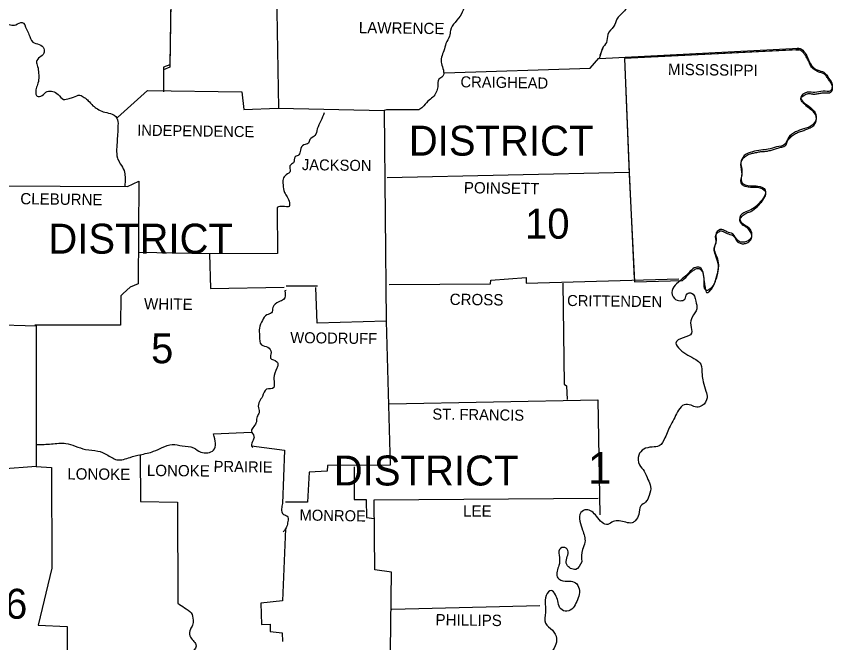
# Model space of a CAD drawing. Extents: x 191 to 3403, y 68 to 2102.
# Drawn here: x 2999.8 to 3303.9, y 1667 to 1900.2 of the extents above; entities that cross this region are included whole.
import ezdxf

# ---------------------------------------------------------------- set-up
doc = ezdxf.new("R2010")
doc.units = 0
for name, color, linetype in [('1', 7, 'Continuous'), ('2', 7, 'Continuous'), ('3', 7, 'Continuous'), ('S_MISC_BOUNDARY', 7, 'Continuous')]:
    doc.layers.add(name, color=color, linetype=linetype)

msp = doc.modelspace()

# ---------------------------------------------------------------- linework, layer by layer
at = {"layer": '1'}
for p, q in [((3216.98, 1884.51), (3218.15, 1888.13)), ((3217.27, 1885.68), (3218.45, 1888.52)), ((3100.35, 1799.78), (3112, 1799.78))]:
    msp.add_line(p, q, dxfattribs=at)
for points in [[(3000.75, 1956.03), (3000.95, 1932.74), (2999.28, 1932.64), (2999.58, 1908.28), (2992.73, 1907.3), (2993.32, 1900.75), (2995.66, 1897.71), (2995.47, 1889.98), (2982.16, 1889.5), (2981.67, 1877.56), (2969.54, 1877.17), (2968.95, 1862.69), (2969.64, 1861.51), (2969.93, 1838.42), (2990.87, 1837.05), (2990.58, 1785.49), (3007.21, 1785), (3007.21, 1732.56), (2994.1, 1731.58), (2993.12, 1720.04), (2971.11, 1719.94)], [(3090.67, 1957.4), (3090.37, 1955.05), (3092.33, 1954.76), (3092.23, 1953.58), (3094.48, 1953.09), (3094.68, 1951.53), (3095.75, 1950.84), (3096.05, 1946.15), (3101.63, 1945.56), (3101.63, 1941.35), (3103.68, 1941.06), (3103.68, 1939.39), (3105.44, 1938.9), (3105.34, 1933.23), (3106.91, 1932.94), (3107.3, 1920.12), (3098.98, 1919.34), (3099.08, 1916.6), (3096.54, 1916.5), (3097.42, 1866.01), (3136.85, 1865.13), (3137.53, 1786.66), (3111.8, 1785.98), (3111.31, 1799.19)], [(3055.64, 1918.95), (3055.44, 1913.27), (3058.18, 1913.07), (3058.28, 1906.81), (3057.3, 1906.81), (3056.91, 1882.16), (3054.66, 1881.18), (3054.66, 1872.96)], [(3055.64, 1918.06), (3055.44, 1912.39), (3058.18, 1912.19), (3058.28, 1905.93), (3057.3, 1905.93), (3056.91, 1881.28), (3054.66, 1880.3), (3054.66, 1872.08)], [(3216.98, 1884.51), (3291.24, 1888.32)], [(3159.25, 1879.12), (3213.55, 1880.89), (3216.78, 1884.6)], [(3226.37, 1884.41), (3228.04, 1842.04), (3229.99, 1802.61)], [(3037.44, 1862.49), (3048.6, 1872.57), (3083.82, 1872.08), (3084.5, 1865.52), (3097.32, 1866.01)], [(3149.67, 1865.33), (3137.73, 1865.33), (3136.85, 1865.13)], [(3228.04, 1842.04), (3137.92, 1839.99)], [(2990.87, 1837.05), (3041.16, 1836.76), (3045.46, 1838.81), (3045.17, 1800.56), (3042.24, 1799.29), (3039.59, 1797.04), (3038.71, 1796.16), (3038.62, 1785.2), (3006.62, 1785.2)], [(3096.93, 1829.03), (3097.12, 1811.81), (3071.69, 1811.71), (3045.56, 1812.2)], [(3071.69, 1811.71), (3072.08, 1798.89), (3099.57, 1799.38)], [(3138.71, 1800.36), (3176.47, 1800.56), (3176.57, 1801.93), (3189.68, 1802.91), (3189.68, 1800.85), (3246.63, 1802.42)], [(3203.38, 1800.85), (3203.87, 1763.18), (3204.75, 1762.6), (3205.04, 1757.51)], [(3100.35, 1798.11), (3099.86, 1798.01)], [(3137.53, 1786.66), (3139, 1733.05), (3115.71, 1732.95), (3115.62, 1730.8), (3108.87, 1730.41), (3108.28, 1719.25), (3100.06, 1719.25)], [(3138.71, 1755.85), (3216.39, 1757.41)], [(3216.39, 1757.41), (3217.18, 1714.56)], [(3073.25, 1744.69), (3087.44, 1745.38)], [(3087.44, 1740.29), (3099.67, 1738.72), (3098.98, 1718.76)], [(3045.86, 1737.06), (3046.05, 1719.55), (3059.85, 1719.25), (3059.95, 1681.68)], [(3007.21, 1732.56), (3012.88, 1732.17), (3012.98, 1694.79), (3007.89, 1673.56), (3018.75, 1673.07), (3018.66, 1655.07)], [(3125.69, 1732.46), (3125.6, 1720.33), (3130.1, 1720.33), (3130.29, 1713.58), (3133.13, 1713.28)], [(3138.71, 1633.54), (3146.34, 1634.03), (3146.24, 1653.9), (3139.1, 1654.38), (3139.49, 1693.23), (3133.33, 1694.11), (3133.13, 1720.23), (3216.59, 1720.82)], [(3100.06, 1709.37), (3098.89, 1682.56), (3090.86, 1681.68), (3091.06, 1673.76), (3094.29, 1673.85), (3094.39, 1671.11), (3098.79, 1670.63), (3098.89, 1667.4)], [(3139.69, 1679.43), (3194.87, 1680.8)]]:
    msp.add_lwpolyline(points, dxfattribs=at)
for points in [[(3240.46, 1960.92), (3240.95, 1956.61), (3242.32, 1954.36), (3242.52, 1950.25), (3244.18, 1948.49), (3247.02, 1946.73), (3249.56, 1943.89), (3250.15, 1940.57), (3249.36, 1937.14), (3249.17, 1933.33), (3248.78, 1930), (3248.19, 1926.97), (3245.84, 1924.52), (3243.59, 1922.76), (3241.54, 1920.71), (3240.07, 1918.55), (3237.53, 1916.21), (3234.98, 1913.76), (3232.93, 1911.61), (3230.87, 1908.87), (3229.89, 1905.83), (3227.64, 1903.68), (3225.88, 1901.73), (3223.53, 1899.08), (3222.36, 1896.44), (3220.11, 1893.41), (3219.62, 1890.47), (3218.15, 1888.13), (3218.06, 1887.73)], [(3168.25, 1906.13), (3166.79, 1903.78), (3165.61, 1901.04), (3163.26, 1897.91), (3161.5, 1894.88), (3161.21, 1892.82), (3159.84, 1890.08), (3159.06, 1887.34), (3158.18, 1884.99), (3158.18, 1882.55), (3158.86, 1880.1), (3158.67, 1877.85), (3157.2, 1876.78), (3156.81, 1873.94), (3156.22, 1871.98), (3154.95, 1870.03), (3153.09, 1868.56), (3151.13, 1866.31), (3149.67, 1865.33)], [(2995.66, 1897.71), (2999.58, 1897.03), (3001.93, 1897.91), (3003.59, 1895.37), (3004.47, 1893.41), (3005.94, 1890.57), (3008.29, 1889.69), (3010.05, 1888.13), (3010.05, 1886.46), (3008.48, 1884.9), (3007.31, 1883.33), (3007.7, 1881.47), (3008.09, 1878.93), (3008.09, 1876.48), (3007.5, 1874.23), (3007.01, 1872.18), (3007.5, 1870.42), (3009.36, 1870.71), (3011.32, 1872.18), (3013.37, 1872.18), (3015.33, 1871.1), (3017.38, 1869.24), (3019.44, 1869.63), (3021.1, 1870.12), (3023.45, 1870.81), (3025.11, 1869.93), (3026.58, 1868.75), (3028.34, 1866.89), (3030.01, 1865.72), (3032.16, 1864.64), (3034.8, 1863.96), (3037.25, 1862.3), (3037.64, 1859.46), (3037.54, 1857.01), (3037.34, 1853.98), (3037.15, 1850.65), (3037.44, 1847.42), (3038.52, 1845.27), (3039.89, 1842.73), (3040.28, 1840.38), (3040.18, 1836.66)], [(3290.16, 1888.22), (3291.24, 1888.32), (3294.57, 1884.8), (3296.03, 1881.86), (3298.19, 1880.2), (3300.63, 1879.32), (3302.49, 1877.07), (3303.76, 1874.62), (3303.08, 1872.47), (3300.34, 1872.28), (3297.31, 1871.79), (3294.37, 1871.88), (3292.02, 1869.93), (3294.18, 1867.29), (3297.01, 1864.84), (3297.8, 1862.2), (3296.23, 1859.65), (3293.1, 1858.28), (3290.07, 1857.11), (3287.33, 1854.76), (3286.05, 1852.51), (3283.02, 1851.53), (3279.89, 1850.65), (3277.15, 1850.36), (3274.02, 1849.77), (3270.99, 1848.3), (3269.72, 1845.76), (3270.11, 1842.14), (3270.01, 1838.32), (3273.24, 1837.05), (3276.08, 1836.95), (3278.81, 1835.49), (3278.52, 1833.33), (3276.47, 1830.6), (3274.02, 1828.44), (3271.57, 1827.37), (3269.32, 1825.31), (3270.11, 1823.26), (3272.16, 1821.89), (3273.63, 1819.64), (3273.43, 1817.58), (3271.09, 1816.11), (3268.54, 1816.7), (3266.68, 1819.15), (3264.53, 1819.93), (3262.67, 1820.81), (3260.52, 1819.54), (3260.52, 1816.7), (3259.74, 1813.67), (3260.42, 1811.42), (3261.3, 1808.29), (3261.2, 1805.94), (3260.42, 1802.61), (3258.76, 1799.19), (3256.8, 1798.11), (3256.02, 1801.83), (3255.63, 1804.86), (3254.45, 1806.62), (3252.89, 1806.72), (3250.83, 1805.25), (3248.58, 1803), (3245.74, 1800.56), (3244.08, 1798.11), (3244.96, 1795.08), (3247.11, 1794.3), (3248.78, 1794.88), (3249.66, 1796.84), (3251.32, 1797.13), (3252.89, 1794.1)], [(3114.44, 1864.25), (3113.27, 1861.22), (3111.9, 1858.28), (3111.02, 1855.74), (3109.16, 1854.27), (3108.57, 1852.9), (3106.91, 1852.32), (3105.64, 1850.36), (3105.05, 1848.6), (3103.68, 1847.82), (3103, 1845.66), (3101.72, 1844.49), (3101.82, 1842.53), (3100.35, 1841.16), (3099.18, 1839.6), (3099.18, 1837.44), (3099.67, 1834.61), (3100.65, 1832.94), (3101.53, 1830.79), (3101.43, 1829.42), (3098.98, 1829.42), (3096.93, 1829.03)], [(3099.86, 1798.01), (3099.37, 1794.79), (3097.52, 1793.91), (3095.36, 1791.75), (3094.87, 1789.8), (3093.11, 1789.01), (3091.45, 1786.96), (3090.37, 1784.12), (3090.37, 1781.19), (3091.06, 1777.86), (3093.5, 1776.98), (3094.68, 1775.02), (3094.48, 1772.97), (3096.83, 1771.6), (3097.22, 1770.42), (3096.83, 1769.15), (3095.75, 1765.53), (3095.85, 1763.09), (3095.66, 1762.01), (3093.02, 1761.32), (3091.45, 1758.68), (3090.37, 1756.82), (3089.98, 1754.38), (3090.28, 1752.62), (3089.49, 1751.25), (3089.2, 1749.19), (3088.22, 1747.43), (3087.34, 1745.77), (3088.32, 1743.81), (3088.03, 1742.44), (3087.44, 1740.29), (3087.93, 1739.6)], [(3252.89, 1794.1), (3253.28, 1791.26), (3251.62, 1788.23), (3251.03, 1785.2), (3251.32, 1782.16), (3248.19, 1780.5), (3245.45, 1778.54), (3247.02, 1776.2), (3249.95, 1774.04), (3252.89, 1772.38), (3254.75, 1770.72), (3255.24, 1766.71), (3255.72, 1764.16), (3256.7, 1760.64), (3257.09, 1758.19), (3255.33, 1755.26), (3253.28, 1754.67), (3251.13, 1755.36), (3248.58, 1755.55), (3246.53, 1753.59), (3245.06, 1750.86), (3243.59, 1748.12), (3242.52, 1745.77), (3241.44, 1743.22), (3239.29, 1740.29), (3236.65, 1739.8), (3233.51, 1739.02), (3231.66, 1736.86), (3231.95, 1733.24), (3233.71, 1730.8), (3235.08, 1727.76), (3236.06, 1725.12), (3235.57, 1721.8), (3234.2, 1719.35), (3232.44, 1717.88), (3231.66, 1714.75), (3230.38, 1712.4), (3229.21, 1711.62), (3226.86, 1711.82), (3224.32, 1712.31), (3222.16, 1712.11), (3220.11, 1711.03), (3218.06, 1711.72), (3215.9, 1714.07), (3214.14, 1715.83), (3212.19, 1716.51), (3210.13, 1715.44), (3209.74, 1712.21), (3210.72, 1708.88), (3211.6, 1704.38), (3210.72, 1701.64), (3210.42, 1697.14)], [(3007.4, 1740.78), (3012.88, 1740.97), (3018.26, 1741.17), (3021.69, 1740.19), (3025.6, 1738.92), (3030.2, 1738.33), (3033.43, 1737.06), (3037.25, 1735.1), (3042.14, 1735.98), (3045.95, 1736.96), (3050.94, 1738.23), (3054.17, 1739.6), (3057.89, 1740.78), (3061.61, 1740.29), (3065.82, 1739.51), (3068.46, 1737.94), (3073.25, 1738.63), (3073.25, 1744.69)], [(3098.98, 1718.76), (3098.59, 1716.81), (3099.37, 1714.75), (3100.74, 1714.07), (3100.94, 1712.11), (3100.45, 1710.15), (3100.06, 1709.37), (3099.18, 1708.2)], [(3210.42, 1697.14), (3208.17, 1694.3), (3204.85, 1696.06), (3204.85, 1698.41), (3205.34, 1700.86), (3204.16, 1702.42), (3202.11, 1701.74), (3202.11, 1698.71), (3201.91, 1695.77), (3201.32, 1691.56), (3202.69, 1690.29), (3205.83, 1689.9), (3208.08, 1689.31), (3209.45, 1687.06), (3209.35, 1684.32), (3208.27, 1681.68), (3206.71, 1679.53), (3204.26, 1678.75), (3202.3, 1680.02), (3201.52, 1682.56), (3200.64, 1684.81), (3198.98, 1686.48), (3197.22, 1684.62), (3196.82, 1681.19), (3196.92, 1678.26), (3196.92, 1674.25), (3199.47, 1671.6), (3201.03, 1668.57), (3200.54, 1665.83), (3198.68, 1662.6), (3197.9, 1659.77), (3197.12, 1655.95), (3197.22, 1651.74), (3196.53, 1647.63), (3195.16, 1644.89), (3192.62, 1642.64), (3190.95, 1641.18), (3189.58, 1639.71), (3188.9, 1636.77), (3188.41, 1634.72), (3186.55, 1632.27), (3185.08, 1632.08), (3183.91, 1633.05), (3183.52, 1634.72), (3183.52, 1636.38), (3182.74, 1638.04), (3180.29, 1638.73), (3178.33, 1638.63), (3177.45, 1637.26), (3178.72, 1633.45), (3179.21, 1631), (3178.53, 1627.67), (3178.92, 1627.28), (3175.4, 1625.42), (3172.56, 1625.13), (3170.21, 1624.44), (3167.96, 1622.98), (3166.88, 1620.82), (3165.32, 1619.06), (3163.95, 1617.4), (3162.09, 1616.62), (3160.04, 1617.01), (3157.3, 1617.3), (3155.73, 1615.35), (3156.22, 1612.51), (3158.08, 1610.85), (3160.82, 1610.06), (3163.66, 1610.26), (3166.4, 1610.55), (3168.94, 1609.18), (3168.45, 1606.54), (3166, 1605.27), (3162.38, 1604.88), (3159.45, 1605.17), (3155.93, 1604.39), (3154.17, 1602.14), (3155.14, 1598.71), (3158.96, 1597.34), (3160.72, 1594.11), (3160.82, 1591.08), (3159.55, 1587.07), (3157.79, 1585.21), (3154.36, 1584.43), (3151.72, 1583.94), (3151.33, 1579.44), (3150.15, 1577.19), (3148.1, 1576.5), (3145.16, 1577.97), (3143.4, 1578.66), (3141.25, 1579.63), (3138.51, 1581.3), (3136.46, 1581), (3137.04, 1576.7), (3137.24, 1576.5), (3139.59, 1573.27), (3141.94, 1570.73), (3143.01, 1567.7)], [(3059.95, 1681.68), (3062.39, 1680.02), (3064.93, 1678.06), (3065.62, 1675.42), (3065.42, 1673.56), (3064.64, 1672), (3064.45, 1669.55), (3065.62, 1667.79), (3066.7, 1666.32), (3065.62, 1663.68), (3063.76, 1661.23), (3062.78, 1658.49), (3062.1, 1654.38)]]:
    msp.add_spline(points, degree=3, dxfattribs=at)
at = {"layer": 'S_MISC_BOUNDARY'}
for p, q in [((3290.19, 1887.64), (3291.26, 1887.74)), ((3290.35, 1887.66), (3290.19, 1887.64)), ((3291.26, 1887.74), (3290.35, 1887.66))]:
    msp.add_line(p, q, dxfattribs=at)
for points in [[(3291.26, 1887.74), (3226.37, 1884.41), (3228.06, 1841.46), (3230.05, 1801.38), (3247.99, 1801.87)], [(3290.18, 1887.69), (3226.37, 1884.41), (3228.06, 1841.46), (3230.05, 1801.38), (3247.99, 1801.87)], [(3290.19, 1887.64), (3290.18, 1887.69)]]:
    msp.add_lwpolyline(points, dxfattribs=at)
for points in [[(3247.99, 1801.87), (3248.6, 1802.42), (3250.86, 1804.68), (3251.84, 1805.47), (3252.37, 1805.82), (3252.91, 1806.14), (3253.69, 1806.32), (3254.48, 1806.05), (3254.9, 1805.67), (3255.24, 1805.25), (3255.49, 1804.79), (3255.65, 1804.28), (3255.77, 1803.53), (3255.86, 1802.77), (3256.04, 1801.25), (3256.36, 1799.36), (3256.82, 1797.53), (3256.96, 1797.35), (3257.17, 1797.32), (3257.74, 1797.56), (3258.78, 1798.61), (3259.28, 1799.44), (3259.73, 1800.28), (3260.12, 1801.14), (3260.44, 1802.03), (3261.23, 1805.36), (3261.32, 1807.71), (3260.44, 1810.84), (3259.76, 1813.09), (3259.75, 1813.84), (3259.99, 1814.6), (3260.31, 1815.36), (3260.54, 1816.12), (3260.55, 1816.47), (3260.5, 1816.82), (3260.33, 1817.54), (3260.27, 1818.25), (3260.54, 1818.96), (3260.78, 1819.26), (3261.03, 1819.54), (3261.57, 1819.99), (3262.13, 1820.25), (3262.69, 1820.23), (3263.16, 1820.05), (3263.62, 1819.81), (3264.09, 1819.57), (3264.55, 1819.35), (3266.71, 1818.57), (3267.26, 1818.1), (3267.65, 1817.41), (3268.03, 1816.7), (3268.56, 1816.12), (3269.82, 1815.58), (3271.11, 1815.54), (3272.35, 1816.02), (3272.93, 1816.44), (3273.46, 1817), (3273.65, 1819.06), (3272.18, 1821.31), (3271.7, 1821.7), (3271.16, 1821.99), (3270.62, 1822.29), (3270.13, 1822.68), (3269.42, 1823.7), (3269.35, 1824.73), (3269.76, 1825.31), (3270.3, 1825.85), (3271.6, 1826.79), (3272.21, 1827.09), (3272.84, 1827.31), (3273.46, 1827.55), (3274.04, 1827.86), (3276.49, 1830.02), (3277.07, 1830.67), (3277.59, 1831.34), (3278.54, 1832.76), (3279.02, 1833.83), (3279.05, 1834.4), (3278.84, 1834.91), (3278.56, 1835.21), (3278.26, 1835.47), (3277.59, 1835.89), (3276.1, 1836.38), (3275.39, 1836.45), (3274.68, 1836.44), (3273.97, 1836.42), (3273.26, 1836.47), (3272.37, 1836.59), (3271.48, 1836.75), (3270.67, 1837.09), (3270.03, 1837.75), (3269.91, 1837.98), (3269.82, 1838.22), (3269.73, 1838.69), (3269.82, 1839.65), (3270.04, 1840.61), (3270.13, 1841.56), (3270.04, 1842.47), (3269.9, 1843.37), (3269.78, 1844.28), (3269.74, 1845.18), (3269.83, 1845.87), (3270.08, 1846.53), (3271.01, 1847.73), (3271.37, 1848.02), (3271.73, 1848.28), (3272.47, 1848.69), (3273.24, 1848.98), (3274.04, 1849.19), (3275.6, 1849.52), (3277.17, 1849.78), (3277.86, 1849.85), (3278.55, 1849.9), (3279.91, 1850.07), (3281.49, 1850.49), (3283.04, 1850.95), (3284.57, 1851.4), (3286.08, 1851.93), (3286.53, 1852.34), (3286.79, 1852.95), (3287.01, 1853.61), (3287.35, 1854.18), (3287.97, 1854.85), (3288.61, 1855.5), (3290.09, 1856.53), (3291.6, 1857.13), (3293.12, 1857.7), (3294.7, 1858.33), (3296.25, 1859.07), (3296.86, 1859.56), (3297.32, 1860.2), (3297.82, 1861.62), (3297.85, 1862.28), (3297.72, 1862.97), (3297.45, 1863.65), (3297.04, 1864.26), (3296.35, 1864.94), (3295.63, 1865.52), (3294.9, 1866.08), (3294.2, 1866.71), (3292.87, 1868.02), (3292.33, 1868.69), (3292.05, 1869.35), (3292.04, 1869.49), (3292.06, 1869.64), (3292.21, 1869.93), (3292.79, 1870.48), (3293.58, 1870.95), (3294.39, 1871.3), (3294.76, 1871.4), (3295.13, 1871.42), (3295.87, 1871.34), (3296.6, 1871.22), (3297.33, 1871.21), (3298.85, 1871.45), (3300.36, 1871.7), (3301.04, 1871.71), (3301.73, 1871.65), (3302.42, 1871.66), (3303.1, 1871.89), (3303.23, 1871.98), (3303.35, 1872.08), (3303.56, 1872.32), (3303.81, 1872.88), (3303.79, 1874.04), (3303.25, 1875.28), (3302.51, 1876.49), (3301.66, 1877.7), (3300.66, 1878.74), (3300.09, 1879.05), (3299.46, 1879.23), (3298.81, 1879.38), (3298.21, 1879.62), (3296.06, 1881.28), (3295.61, 1881.98), (3295.29, 1882.73), (3294.98, 1883.49), (3294.59, 1884.22), (3293.9, 1885.31), (3293.18, 1886.38), (3292.33, 1887.25), (3291.83, 1887.56), (3291.55, 1887.67), (3291.26, 1887.74), (3290.19, 1887.64)], [(3296.38, 1871.25), (3296.6, 1871.22), (3297.33, 1871.21), (3298.85, 1871.45), (3300.36, 1871.7), (3301.04, 1871.71), (3301.73, 1871.65), (3302.42, 1871.66), (3303.1, 1871.89), (3303.23, 1871.98), (3303.35, 1872.08), (3303.56, 1872.32), (3303.81, 1872.88), (3303.79, 1874.04), (3303.25, 1875.28), (3302.51, 1876.49), (3301.66, 1877.7), (3300.66, 1878.74), (3300.09, 1879.05), (3299.46, 1879.23), (3298.81, 1879.38), (3298.21, 1879.62), (3296.06, 1881.28), (3295.61, 1881.98), (3295.29, 1882.73), (3294.98, 1883.49), (3294.59, 1884.22), (3293.9, 1885.31), (3293.18, 1886.38), (3292.33, 1887.25), (3291.83, 1887.56), (3291.55, 1887.67), (3291.26, 1887.74)], [(3286.92, 1853.33), (3287.01, 1853.61), (3287.35, 1854.18), (3287.97, 1854.85), (3288.61, 1855.5), (3290.09, 1856.53), (3291.6, 1857.13), (3293.12, 1857.7), (3294.7, 1858.33), (3296.25, 1859.07), (3296.86, 1859.56), (3297.32, 1860.2), (3297.82, 1861.62), (3297.85, 1862.28), (3297.72, 1862.97), (3297.45, 1863.65), (3297.04, 1864.26), (3296.35, 1864.94), (3295.63, 1865.52), (3294.9, 1866.08), (3294.2, 1866.71), (3292.87, 1868.02), (3292.33, 1868.69), (3292.05, 1869.35), (3292.04, 1869.49), (3292.06, 1869.64), (3292.21, 1869.93), (3292.79, 1870.48), (3293.58, 1870.95), (3294.39, 1871.3), (3294.76, 1871.4), (3295.13, 1871.42), (3295.87, 1871.34), (3296.38, 1871.25)], [(3271.36, 1836.78), (3270.67, 1837.09), (3270.03, 1837.75), (3269.91, 1837.98), (3269.82, 1838.22), (3269.73, 1838.69), (3269.82, 1839.65), (3270.04, 1840.61), (3270.13, 1841.56), (3270.04, 1842.47), (3269.9, 1843.37), (3269.78, 1844.28), (3269.74, 1845.18), (3269.83, 1845.87), (3270.08, 1846.53), (3271.01, 1847.73), (3271.37, 1848.02), (3271.73, 1848.28), (3272.47, 1848.69), (3273.24, 1848.98), (3274.04, 1849.19), (3275.6, 1849.52), (3277.17, 1849.78), (3277.86, 1849.85), (3278.55, 1849.9), (3279.91, 1850.07), (3281.49, 1850.49), (3283.04, 1850.95), (3284.57, 1851.4), (3286.08, 1851.93), (3286.53, 1852.34), (3286.79, 1852.95), (3286.92, 1853.33)], [(3273.44, 1819.54), (3272.18, 1821.31), (3271.7, 1821.7), (3271.16, 1821.99), (3270.62, 1822.29), (3270.13, 1822.68), (3269.42, 1823.7), (3269.35, 1824.73), (3269.76, 1825.31), (3270.3, 1825.85), (3271.6, 1826.79), (3272.21, 1827.09), (3272.84, 1827.31), (3273.46, 1827.55), (3274.04, 1827.86), (3276.49, 1830.02), (3277.07, 1830.67), (3277.59, 1831.34), (3278.54, 1832.76), (3279.02, 1833.83), (3279.05, 1834.4), (3278.84, 1834.91), (3278.56, 1835.21), (3278.26, 1835.47), (3277.59, 1835.89), (3276.1, 1836.38), (3275.39, 1836.45), (3274.68, 1836.44), (3273.97, 1836.42), (3273.26, 1836.47), (3272.37, 1836.59), (3271.48, 1836.75), (3271.36, 1836.78)], [(3261.26, 1807.98), (3260.44, 1810.84), (3259.76, 1813.09), (3259.75, 1813.84), (3259.99, 1814.6), (3260.31, 1815.36), (3260.54, 1816.12), (3260.55, 1816.47), (3260.5, 1816.82), (3260.33, 1817.54), (3260.27, 1818.25), (3260.54, 1818.96), (3260.78, 1819.26), (3261.03, 1819.54), (3261.57, 1819.99), (3262.13, 1820.25), (3262.69, 1820.23), (3263.16, 1820.05), (3263.62, 1819.81), (3264.09, 1819.57), (3264.55, 1819.35), (3266.71, 1818.57), (3267.26, 1818.1), (3267.65, 1817.41), (3268.03, 1816.7), (3268.56, 1816.12), (3269.82, 1815.58), (3271.11, 1815.54), (3272.35, 1816.02), (3272.93, 1816.44), (3273.46, 1817), (3273.65, 1819.06), (3273.44, 1819.54)], [(3247.99, 1801.87), (3248.6, 1802.42), (3250.86, 1804.68), (3251.84, 1805.47), (3252.37, 1805.82), (3252.91, 1806.14), (3253.69, 1806.32), (3254.48, 1806.05), (3254.9, 1805.67), (3255.24, 1805.25), (3255.49, 1804.79), (3255.65, 1804.28), (3255.77, 1803.53), (3255.86, 1802.77), (3256.04, 1801.25), (3256.36, 1799.36), (3256.82, 1797.53), (3256.96, 1797.35), (3257.17, 1797.32), (3257.74, 1797.56), (3258.78, 1798.61), (3259.28, 1799.44), (3259.73, 1800.28), (3260.12, 1801.14), (3260.44, 1802.03), (3261.23, 1805.36), (3261.32, 1807.71), (3261.26, 1807.98)]]:
    msp.add_spline(points, degree=3, dxfattribs=at)

# ---------------------------------------------------------------- texts
at = {"layer": '1'}
msp.add_text('1', height=11.74, dxfattribs=at).set_placement((3212.77, 1726.2))
at = {"layer": '2'}
for s, height, rotation, p in [('LAWRENCE', 4.207, 359.2678, (3127.36, 1893.9)), ('MISSISSIPPI', 4.2062, 359.3097, (3242.52, 1878.34)), ('CRAIGHEAD', 4.109, 359.1159, (3165.22, 1873.74)), ('INDEPENDENCE', 4.1081, 359.2187, (3044.78, 1855.74)), ('JACKSON', 4.108, 359.1352, (3106.13, 1842.92)), ('POINSETT', 4.206, 359.1987, (3166.49, 1834.31)), ('CLEBURNE', 4.206, 359.2535, (3001.24, 1830.2)), ('WHITE', 4.207, 359.3139, (3047.32, 1791.07)), ('CROSS', 4.206, 359.3839, (3161.21, 1792.73)), ('CRITTENDEN', 4.109, 359.213, (3204.94, 1792.34)), ('WOODRUFF', 4.108, 359.2748, (3101.82, 1778.54)), ('ST. FRANCIS', 4.1081, 359.2216, (3154.75, 1750.07)), ('PRAIRIE', 4.109, 359.2116, (3073.25, 1730.6)), ('LONOKE', 4.207, 359.4974, (3018.75, 1727.76)), ('LONOKE', 4.207, 359.4974, (3048.4, 1729.04)), ('MONROE', 4.108, 359.0331, (3105.25, 1712.5)), ('LEE', 4.207, 359.4327, (3166.2, 1713.97)), ('PHILLIPS', 4.206, 359.3179, (3155.93, 1673.46))]:
    msp.add_text(s, height=height, rotation=rotation, dxfattribs=at).set_placement(p)
at = {"layer": '3'}
for s, height, p in [('DISTRICT', 11.154, (3146, 1848.31)), ('10', 11.154, (3189.29, 1817.39)), ('DISTRICT', 11.154, (3011.71, 1811.81)), ('5', 11.15, (3049.97, 1771.01)), ('DISTRICT', 11.154, (3118.06, 1725.51)), ('DISTRICT 6', 11.154, (2922.67, 1675.91))]:
    msp.add_text(s, height=height, dxfattribs=at).set_placement(p)

doc.saveas('drawing.dxf')
